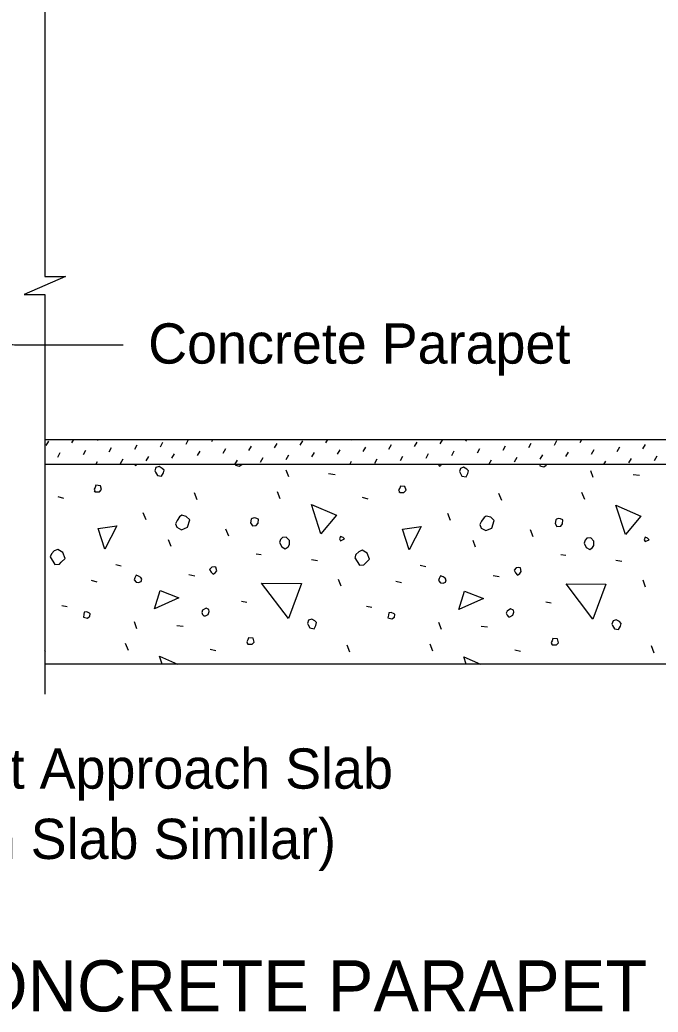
# Model space of a CAD drawing. Extents: x 110341.7 to 110413.5, y 110387.3 to 110417.8.
# Drawn here: x 110357.09 to 110360.284, y 110400.976 to 110405.944 of the extents above; entities that cross this region are included whole.
import ezdxf

# ---------------------------------------------------------------- set-up
doc = ezdxf.new("R2010")
doc.units = 0
for name, color, linetype in [('Border', 7, 'Continuous'), ('Patterning', 7, 'Continuous'), ('PlotBorder_dp', 7, 'Continuous'), ('SheetBorder_dp', 7, 'Continuous')]:
    doc.layers.add(name, color=color, linetype=linetype)

msp = doc.modelspace()

# ---------------------------------------------------------------- linework, layer by layer
at = {"layer": 'Border'}
msp.add_lwpolyline([(110357.2147, 110406.5102), (110357.2147, 110404.6594), (110357.3181, 110404.6594), (110357.2147, 110404.6144), (110357.1114, 110404.5694), (110357.2147, 110404.5694), (110357.2147, 110402.5685)], dxfattribs=at)
msp.add_open_spline([(110357.6069, 110404.3154), (110357.447, 110404.3154), (110356.7476, 110404.3154), (110356.1899, 110404.5723)], degree=2, dxfattribs=at)
at = {"layer": 'Patterning'}
for p, q in [((110357.2215, 110403.8128), (110357.2345, 110403.8352)), ((110357.35, 110403.8258), (110357.3602, 110403.8435)), ((110357.4784, 110403.8388), (110357.4812, 110403.8435)), ((110357.9215, 110403.8199), (110357.9345, 110403.8423)), ((110358.05, 110403.8329), (110358.0562, 110403.8435)), ((110358.4931, 110403.814), (110358.5061, 110403.8364)), ((110358.6216, 110403.827), (110358.6312, 110403.8435)), ((110358.75, 110403.8399), (110358.7521, 110403.8435)), ((110359.1932, 110403.8211), (110359.2061, 110403.8435)), ((110359.3216, 110403.834), (110359.3271, 110403.8435)), ((110359.7647, 110403.8152), (110359.7777, 110403.8376)), ((110359.8932, 110403.8282), (110359.9021, 110403.8435)), ((110360.0217, 110403.8411), (110360.0231, 110403.8435)), ((110357.4077, 110403.768), (110357.4207, 110403.7904)), ((110357.5362, 110403.781), (110357.5491, 110403.8034)), ((110357.6646, 110403.794), (110357.6776, 110403.8164)), ((110357.7931, 110403.8069), (110357.8061, 110403.8293)), ((110357.9793, 110403.7622), (110357.9923, 110403.7845)), ((110358.1078, 110403.7751), (110358.1207, 110403.7975)), ((110358.2362, 110403.7881), (110358.2492, 110403.8105)), ((110358.3647, 110403.801), (110358.3776, 110403.8234)), ((110358.6793, 110403.7692), (110358.6923, 110403.7916)), ((110358.8078, 110403.7822), (110358.8208, 110403.8046)), ((110358.9362, 110403.7952), (110358.9492, 110403.8175)), ((110359.0647, 110403.8081), (110359.0777, 110403.8305)), ((110359.2509, 110403.7633), (110359.2639, 110403.7857)), ((110359.3794, 110403.7763), (110359.3923, 110403.7987)), ((110359.5078, 110403.7893), (110359.5208, 110403.8117)), ((110359.6363, 110403.8022), (110359.6492, 110403.8246)), ((110359.9509, 110403.7704), (110359.9639, 110403.7928)), ((110360.0794, 110403.7834), (110360.0924, 110403.8058)), ((110360.2079, 110403.7963), (110360.2208, 110403.8187)), ((110357.2793, 110403.7551), (110357.2922, 110403.7775)), ((110357.4702, 110403.7185), (110357.4784, 110403.7327)), ((110357.5939, 110403.7233), (110357.6069, 110403.7457)), ((110357.7224, 110403.7362), (110357.7353, 110403.7586)), ((110357.8508, 110403.7492), (110357.8638, 110403.7716)), ((110358.1662, 110403.7185), (110358.1785, 110403.7398)), ((110358.294, 110403.7303), (110358.3069, 110403.7527)), ((110358.4224, 110403.7433), (110358.4354, 110403.7657)), ((110358.5509, 110403.7563), (110358.5638, 110403.7787)), ((110358.7412, 110403.7185), (110358.75, 110403.7339)), ((110358.8655, 110403.7244), (110358.8785, 110403.7468)), ((110358.994, 110403.7374), (110359.007, 110403.7598)), ((110359.1225, 110403.7504), (110359.1354, 110403.7728)), ((110359.4371, 110403.7185), (110359.4501, 110403.7409)), ((110359.5656, 110403.7315), (110359.5785, 110403.7539)), ((110359.694, 110403.7445), (110359.707, 110403.7669)), ((110359.8225, 110403.7574), (110359.8355, 110403.7798)), ((110360.0121, 110403.7185), (110360.0217, 110403.735)), ((110360.1371, 110403.7256), (110360.1501, 110403.748)), ((110360.2656, 110403.7386), (110360.2786, 110403.761)), ((110358.4355, 110403.6561), (110358.4231, 110403.6897)), ((110359.9593, 110403.6526), (110359.9469, 110403.6862)), ((110358.6352, 110403.6721), (110358.6671, 110403.6685)), ((110360.159, 110403.6685), (110360.1909, 110403.665)), ((110357.2794, 110403.5571), (110357.3076, 110403.5501)), ((110357.9776, 110403.5412), (110357.9635, 110403.5766)), ((110358.3931, 110403.5465), (110358.3789, 110403.5819)), ((110358.8032, 110403.5536), (110358.8315, 110403.5465)), ((110359.5014, 110403.5377), (110359.4873, 110403.5731)), ((110359.9169, 110403.543), (110359.9027, 110403.5784)), ((110357.7213, 110403.4405), (110357.7072, 110403.4758)), ((110359.2451, 110403.4369), (110359.231, 110403.4723)), ((110358.135, 110403.3592), (110358.1208, 110403.3945)), ((110359.6588, 110403.3556), (110359.6446, 110403.391)), ((110357.8468, 110403.3079), (110357.8344, 110403.3415)), ((110359.3706, 110403.3044), (110359.3583, 110403.3379)), ((110358.2728, 110403.2708), (110358.2976, 110403.2672)), ((110358.5486, 110403.2425), (110358.5787, 110403.2372)), ((110359.7967, 110403.2672), (110359.8214, 110403.2637)), ((110360.0724, 110403.2389), (110360.1025, 110403.2336)), ((110357.5693, 110403.2177), (110357.5976, 110403.2107)), ((110359.0931, 110403.2142), (110359.1214, 110403.2071)), ((110357.4473, 110403.1382), (110357.4756, 110403.1311)), ((110357.9352, 110403.1665), (110357.9653, 110403.1612)), ((110358.6971, 110403.1081), (110358.6847, 110403.1417)), ((110359.459, 110403.1629), (110359.4891, 110403.1576)), ((110360.2209, 110403.1046), (110360.2085, 110403.1382)), ((110358.9711, 110403.1346), (110358.9994, 110403.1276)), ((110357.3006, 110403.0127), (110357.3271, 110403.0074)), ((110358.1986, 110403.0339), (110358.2251, 110403.0286)), ((110358.8244, 110403.0091), (110358.8509, 110403.0038)), ((110359.7224, 110403.0304), (110359.7489, 110403.025)), ((110357.6753, 110402.896), (110357.663, 110402.9296)), ((110357.8751, 110402.9119), (110357.9069, 110402.9084)), ((110359.1992, 110402.8925), (110359.1868, 110402.9261)), ((110359.3989, 110402.9084), (110359.4307, 110402.9048)), ((110357.6329, 110402.7864), (110357.6188, 110402.8218)), ((110358.043, 110402.7935), (110358.0713, 110402.7864)), ((110358.7413, 110402.7776), (110358.7272, 110402.8129)), ((110359.1567, 110402.7829), (110359.1426, 110402.8182)), ((110359.5668, 110402.7899), (110359.5951, 110402.7829)), ((110360.2651, 110402.774), (110360.251, 110402.8094)), ((110357.2175, 110402.7811), (110357.2147, 110402.788))]:
    msp.add_line(p, q, dxfattribs=at)
for points in [[(110357.67, 110403.7109), (110357.6643, 110403.7185)], [(110357.6729, 110403.7185), (110357.67, 110403.7109)], [(110357.769, 110403.6791), (110357.7779, 110403.6632), (110357.7991, 110403.6597), (110357.8079, 110403.6756), (110357.8115, 110403.6897), (110357.8026, 110403.6986), (110357.7867, 110403.7074), (110357.7708, 110403.7021), (110357.7655, 110403.6862), (110357.769, 110403.6791)], [(110358.1685, 110403.7145), (110358.188, 110403.7092), (110358.2004, 110403.718), (110358.2004, 110403.7185)], [(110358.1691, 110403.7185), (110358.1685, 110403.7145)], [(110359.1938, 110403.7074), (110359.1854, 110403.7185)], [(110359.198, 110403.7185), (110359.1938, 110403.7074)], [(110359.2928, 110403.6756), (110359.3017, 110403.6597), (110359.3229, 110403.6561), (110359.3317, 110403.6721), (110359.3353, 110403.6862), (110359.3264, 110403.695), (110359.3105, 110403.7039), (110359.2946, 110403.6986), (110359.2893, 110403.6827), (110359.2928, 110403.6756)], [(110359.6924, 110403.7109), (110359.7118, 110403.7056), (110359.7242, 110403.7145), (110359.7248, 110403.7185)], [(110359.6934, 110403.7185), (110359.6924, 110403.7109)], [(110357.4667, 110403.5819), (110357.488, 110403.5819), (110357.4986, 110403.5925), (110357.4933, 110403.6119), (110357.4703, 110403.6137), (110357.4667, 110403.6031), (110357.4614, 110403.5943), (110357.4667, 110403.5819), (110357.4632, 110403.5854)], [(110358.9906, 110403.5784), (110359.0118, 110403.5784), (110359.0224, 110403.589), (110359.0171, 110403.6084), (110358.9941, 110403.6102), (110358.9906, 110403.5996), (110358.9853, 110403.5907), (110358.9906, 110403.5784), (110358.987, 110403.5819)], [(110358.5963, 110403.3715), (110358.5486, 110403.5183), (110358.6741, 110403.4635), (110358.5963, 110403.3715)], [(110360.1202, 110403.368), (110360.0724, 110403.5147), (110360.1979, 110403.4599), (110360.1202, 110403.368)], [(110357.8751, 110403.4034), (110357.8981, 110403.391), (110357.9281, 110403.4034), (110357.9405, 110403.4405), (110357.9228, 110403.4582), (110357.8998, 110403.4635), (110357.8892, 110403.4564), (110357.8769, 110403.4369), (110357.868, 110403.421), (110357.8751, 110403.4034)], [(110358.2446, 110403.4263), (110358.2534, 110403.4104), (110358.2728, 110403.4122), (110358.2817, 110403.4246), (110358.2834, 110403.444), (110358.2711, 110403.4493), (110358.2622, 110403.4511), (110358.2516, 110403.4475), (110358.2481, 110403.444), (110358.2446, 110403.4263)], [(110359.3989, 110403.3998), (110359.4219, 110403.3874), (110359.4519, 110403.3998), (110359.4643, 110403.4369), (110359.4466, 110403.4546), (110359.4237, 110403.4599), (110359.4131, 110403.4528), (110359.4007, 110403.4334), (110359.3918, 110403.4175), (110359.3989, 110403.3998)], [(110359.7684, 110403.4228), (110359.7772, 110403.4069), (110359.7967, 110403.4087), (110359.8055, 110403.421), (110359.8073, 110403.4405), (110359.7949, 110403.4458), (110359.7861, 110403.4475), (110359.7754, 110403.444), (110359.7719, 110403.4405), (110359.7684, 110403.4228)], [(110357.5145, 110403.2937), (110357.4809, 110403.398), (110357.5746, 110403.4104), (110357.5145, 110403.2937)], [(110359.0383, 110403.2902), (110359.0047, 110403.3945), (110359.0984, 110403.4069), (110359.0383, 110403.2902)], [(110358.3895, 110403.3273), (110358.4001, 110403.3061), (110358.4178, 110403.2955), (110358.4319, 110403.3061), (110358.439, 110403.3167), (110358.439, 110403.3379), (110358.4231, 110403.3539), (110358.4037, 110403.3521), (110358.3948, 110403.3432), (110358.3895, 110403.3273)], [(110358.6953, 110403.3362), (110358.7148, 110403.345), (110358.7077, 110403.3521), (110358.6953, 110403.3574), (110358.69, 110403.345), (110358.6953, 110403.3362)], [(110359.9133, 110403.3238), (110359.9239, 110403.3026), (110359.9416, 110403.292), (110359.9558, 110403.3026), (110359.9628, 110403.3132), (110359.9628, 110403.3344), (110359.9469, 110403.3503), (110359.9275, 110403.3485), (110359.9186, 110403.3397), (110359.9133, 110403.3238)], [(110360.2192, 110403.3326), (110360.2386, 110403.3415), (110360.2315, 110403.3485), (110360.2192, 110403.3539), (110360.2139, 110403.3415), (110360.2192, 110403.3326)], [(110357.2422, 110403.2549), (110357.2652, 110403.2177), (110357.2882, 110403.2195), (110357.297, 110403.2283), (110357.3165, 110403.2478), (110357.3041, 110403.2778), (110357.2794, 110403.292), (110357.2617, 110403.2849), (110357.2475, 110403.2708), (110357.2422, 110403.2549)], [(110358.766, 110403.2513), (110358.789, 110403.2142), (110358.812, 110403.216), (110358.8208, 110403.2248), (110358.8403, 110403.2443), (110358.8279, 110403.2743), (110358.8032, 110403.2884), (110358.7855, 110403.2814), (110358.7714, 110403.2672), (110358.766, 110403.2513)], [(110358.0466, 110403.1788), (110358.0572, 110403.1682), (110358.0678, 110403.1753), (110358.0749, 110403.1859), (110358.0713, 110403.2036), (110358.0625, 110403.2054), (110358.0501, 110403.2036), (110358.0395, 110403.193), (110358.0466, 110403.1788)], [(110359.5704, 110403.1753), (110359.581, 110403.1647), (110359.5916, 110403.1718), (110359.5987, 110403.1824), (110359.5951, 110403.2001), (110359.5863, 110403.2018), (110359.5739, 110403.2001), (110359.5633, 110403.1895), (110359.5704, 110403.1753)], [(110357.6718, 110403.1293), (110357.6842, 110403.1276), (110357.6966, 110403.1329), (110357.7001, 110403.1435), (110357.6948, 110403.1523), (110357.6842, 110403.1594), (110357.6718, 110403.1647), (110357.6647, 110403.1506), (110357.6612, 110403.14), (110357.6718, 110403.1293)], [(110359.1956, 110403.1258), (110359.208, 110403.124), (110359.2204, 110403.1293), (110359.2239, 110403.14), (110359.2186, 110403.1488), (110359.208, 110403.1559), (110359.1956, 110403.1612), (110359.1885, 110403.147), (110359.185, 110403.1364), (110359.1956, 110403.1258)], [(110357.7637, 110402.995), (110357.792, 110403.0869), (110357.8857, 110403.0498), (110357.7637, 110402.995)], [(110358.4337, 110402.9473), (110358.2994, 110403.124), (110358.4991, 110403.1223), (110358.4337, 110402.9473)], [(110359.9575, 110402.9437), (110359.8232, 110403.1205), (110360.0229, 110403.1187), (110359.9575, 110402.9437)], [(110359.2875, 110402.9915), (110359.3158, 110403.0834), (110359.4095, 110403.0463), (110359.2875, 110402.9915)], [(110358.0112, 110402.9596), (110358.0183, 110402.9596), (110358.0324, 110402.9667), (110358.0377, 110402.9826), (110358.036, 110402.9915), (110358.0218, 110402.9985), (110358.0041, 110402.9879), (110358.0006, 110402.9773), (110358.0041, 110402.9667), (110358.0112, 110402.9596)], [(110359.535, 110402.9561), (110359.5421, 110402.9561), (110359.5562, 110402.9632), (110359.5615, 110402.9791), (110359.5598, 110402.9879), (110359.5456, 110402.995), (110359.528, 110402.9844), (110359.5244, 110402.9738), (110359.528, 110402.9632), (110359.535, 110402.9561)], [(110357.4084, 110402.9543), (110357.4278, 110402.949), (110357.4402, 110402.9579), (110357.442, 110402.9702), (110357.4385, 110402.9738), (110357.4243, 110402.9809), (110357.4119, 110402.9791), (110357.4102, 110402.9667), (110357.4084, 110402.9543)], [(110358.5327, 110402.9154), (110358.5415, 110402.8995), (110358.5628, 110402.896), (110358.5716, 110402.9119), (110358.5751, 110402.9261), (110358.5663, 110402.9349), (110358.5504, 110402.9437), (110358.5345, 110402.9384), (110358.5292, 110402.9225), (110358.5327, 110402.9154)], [(110358.9322, 110402.9508), (110358.9517, 110402.9455), (110358.964, 110402.9543), (110358.9658, 110402.9667), (110358.9623, 110402.9702), (110358.9481, 110402.9773), (110358.9358, 110402.9756), (110358.934, 110402.9632), (110358.9322, 110402.9508)], [(110360.0565, 110402.9119), (110360.0654, 110402.896), (110360.0866, 110402.8925), (110360.0954, 110402.9084), (110360.0989, 110402.9225), (110360.0901, 110402.9314), (110360.0742, 110402.9402), (110360.0583, 110402.9349), (110360.053, 110402.919), (110360.0565, 110402.9119)], [(110358.2304, 110402.8182), (110358.2516, 110402.8182), (110358.2622, 110402.8288), (110358.2569, 110402.8483), (110358.234, 110402.85), (110358.2304, 110402.8394), (110358.2251, 110402.8306), (110358.2304, 110402.8182), (110358.2269, 110402.8218)], [(110359.7542, 110402.8147), (110359.7754, 110402.8147), (110359.7861, 110402.8253), (110359.7807, 110402.8447), (110359.7578, 110402.8465), (110359.7542, 110402.8359), (110359.7489, 110402.8271), (110359.7542, 110402.8147), (110359.7507, 110402.8182)], [(110357.8013, 110402.7185), (110357.7885, 110402.7581), (110357.8791, 110402.7185)], [(110359.324, 110402.7185), (110359.3123, 110402.7546), (110359.3948, 110402.7185)]]:
    msp.add_lwpolyline(points, dxfattribs=at)
at = {"layer": 'PlotBorder_dp'}
for p, q in [((110357.2147, 110403.8435), (110364.5166, 110403.8435)), ((110362.5166, 110403.7185), (110357.2147, 110403.7185)), ((110362.8993, 110402.7185), (110357.2147, 110402.7185))]:
    msp.add_line(p, q, dxfattribs=at)

# ---------------------------------------------------------------- texts
at = {"layer": 'Border'}
for s, p in [('Approach Slab (Flexible Pavement Approach Slab ', (110352.9629, 110402.095)), ('Shown, Rigid Pavement Approach Slab Similar)', (110352.9629, 110401.743))]:
    msp.add_text(s, height=0.2016, dxfattribs=at).set_placement(p)
at = {"layer": 'SheetBorder_dp'}
for s, height, p in [('Concrete Parapet', 0.2016, (110357.7321, 110404.2229)), ('ELEVATION AT INSIDE FACE OF CONCRETE PARAPET', 0.256001, (110351.2508, 110400.9799))]:
    msp.add_text(s, height=height, dxfattribs=at).set_placement(p)

doc.saveas('drawing.dxf')
